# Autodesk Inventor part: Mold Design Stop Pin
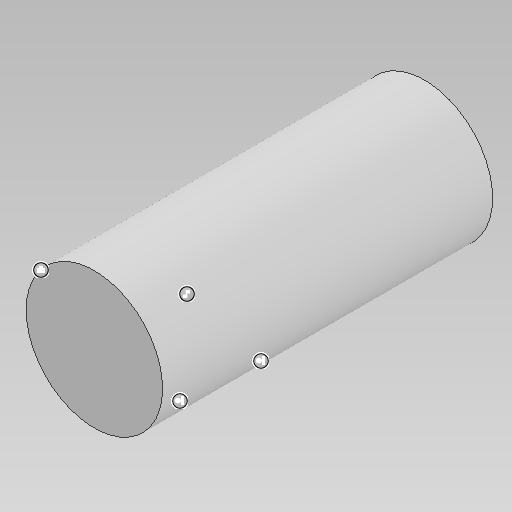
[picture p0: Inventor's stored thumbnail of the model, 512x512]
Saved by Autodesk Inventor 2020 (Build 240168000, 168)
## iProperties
Manager: www.cadconsulting.pl
Company: Fabian Stasiak CAD Consulting
Created: 2007-09
Part Number: Mold Design Stop Pin
Document SubType Name: Modeling
Designer: F.Stasiak
Density: 1 g/cm^3
Material: Generic
Appearance: Default
Author: F.Stasiak
Subject: Zbiór ćwiczeń. Autodesk Inventor 2020. Kurs podstawowy
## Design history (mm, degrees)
sketch "Sketch1"
  geometry: C1 r 4.132 at (0, 0); 1 further point
  constraints: 1 centre point, 1 coincident
  dimensions: "Diameter" = 8.26421 diameter of C1
extrude "Extrusion1" new body sketch "Sketch1" taper "d2" = 0 deg; stored distance "Height" = 20
body "Solid1"
other parameters: "d3" = 0, "d4" = 0, "d9" = 0, "d10" = 0
